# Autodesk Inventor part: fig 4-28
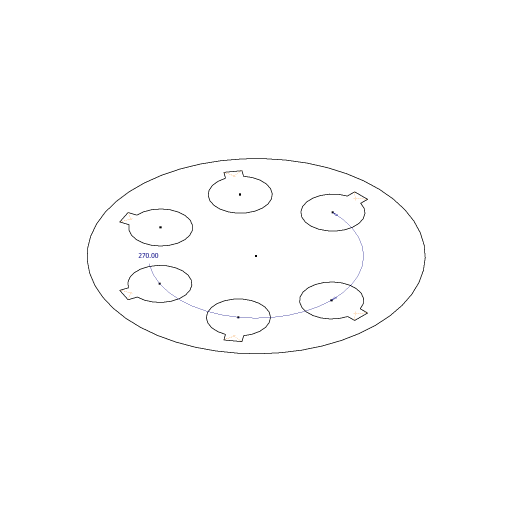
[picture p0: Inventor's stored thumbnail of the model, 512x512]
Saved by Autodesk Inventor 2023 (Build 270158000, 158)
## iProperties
Created: 2004-05
Part Number: fig 4-28
Document SubType Name: Modeling
Designer: CADCIM Technologies
Manufacturer: Standard
Standards Organization: Custom
Density: 1 g/cm^3
Material: Generic
Appearance: Default
Author: CADCIM Technologies
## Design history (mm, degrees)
sketch "Sketch2"
  geometry: L1 (0.73, 11.049)-(0.73, 11.828); L2 (0.73, 11.828)-(-0.73, 11.828); L3 (-0.73, 11.828)-(-0.73, 11.006); L4 (-0.152, 11.061)-(0.73, 11.828); L5 (0.152, 11.061)-(-0.73, 11.828); L6 (-8.51, 7.085)-(-9.14, 7.543); L7 (-9.14, 7.543)-(-9.998, 6.362); L8 (-9.998, 6.362)-(-9.333, 5.879); L9 (-9.038, 6.378)-(-9.14, 7.543); L10 (-8.859, 6.625)-(-9.998, 6.362); L11 (-10.734, -2.72)-(-11.474, -2.961); L12 (-11.474, -2.961)-(-11.023, -4.349); L13 (-11.023, -4.349)-(-10.242, -4.095); L14 (-10.472, -3.563)-(-11.474, -2.961); L15 (-10.566, -3.273)-(-11.023, -4.349); L16 (-4.108, -10.283)-(-4.349, -11.023); L17 (-4.349, -11.023)-(-2.961, -11.474); L18 (-2.961, -11.474)-(-2.707, -10.693); L19 (-3.273, -10.566)-(-4.349, -11.023); L20 (-3.563, -10.472)-(-2.961, -11.474); L21 (5.904, -9.368)-(6.362, -9.998); L22 (6.362, -9.998)-(7.543, -9.14); L23 (7.543, -9.14)-(7.06, -8.475); L24 (6.625, -8.859)-(6.362, -9.998); L25 (6.378, -9.038)-(7.543, -9.14); L26 (11.049, -0.73)-(11.828, -0.73); L27 (11.828, -0.73)-(11.828, 0.73); L28 (11.828, 0.73)-(11.006, 0.73); L29 (11.061, 0.152)-(11.828, -0.73); L30 (11.061, -0.152)-(11.828, 0.73); C1 r 13.473 at (0, 0); A1 r 2.558 centre (0.072, 8.577) between (-0.73, 11.006) and (0.73, 11.049); A2 r 2.558 centre (-6.897, 5.1) between (-9.333, 5.879) and (-8.51, 7.085); A3 r 2.558 centre (-8.18, -2.582) between (-10.242, -4.095) and (-10.734, -2.72); A4 r 2.558 centre (-2.719, -8.135) between (-2.707, -10.693) and (-4.108, -10.283); A5 r 2.558 centre (4.983, -6.981) between (7.06, -8.475) and (5.904, -9.368); A6 r 2.558 centre (8.577, -0.072) between (11.006, 0.73) and (11.049, -0.73); 6 further points
  constraints: 60 end point, 12 point on circle, 7 centre point, 2 coincident, 1 parallel, 70 other
  dimensions: "d6" = 270 deg dimension on point (0, 0) A1.centre A6.centre
